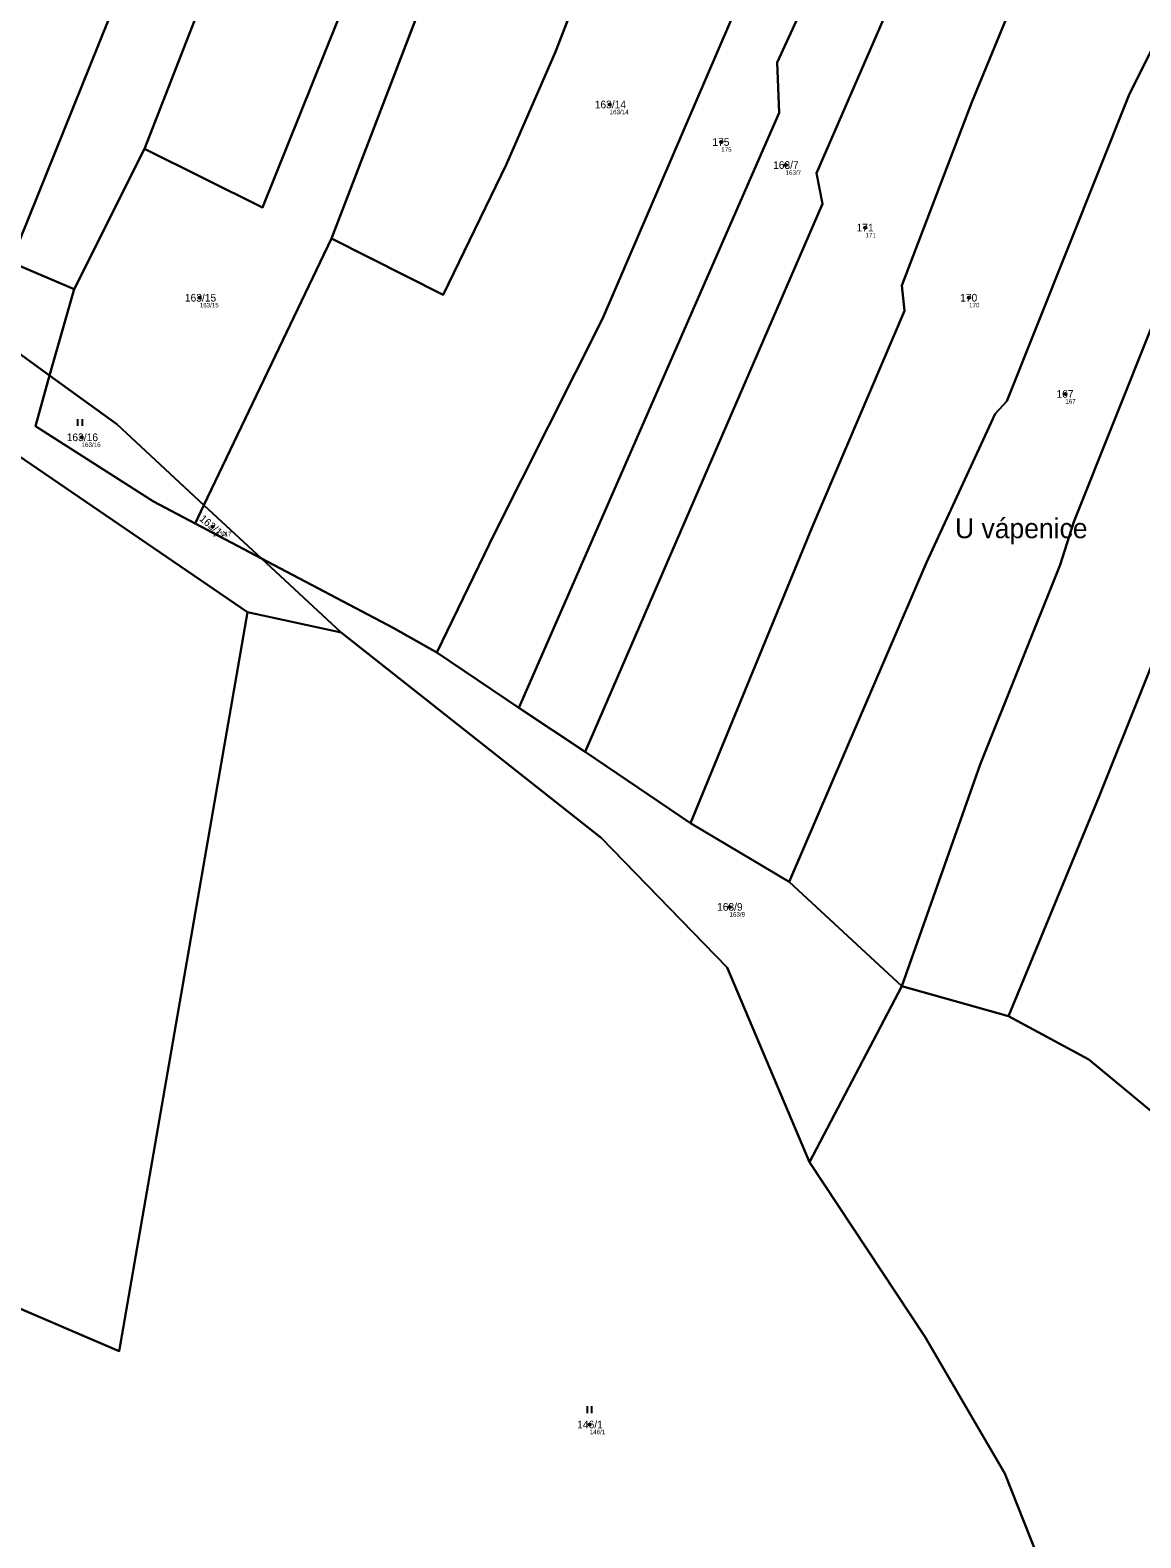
# Model space of a CAD drawing. Extents: x -767985 to -763816, y -1059600 to -1057360.
# Drawn here: x -766260 to -766013.3, y -1058832.2 to -1058497.3 of the extents above; entities that cross this region are included whole.
import ezdxf

# ---------------------------------------------------------------- set-up
doc = ezdxf.new("R2010")
doc.units = 0
for name, color, linetype in [('Definiční body', 7, 'Continuous'), ('Hranice parcel', 7, 'Continuous'), ('Parcelní čísla', 7, 'Continuous'), ('Polygon parcely', 7, 'Continuous'), ('Pop  PČ popisy', 7, 'Continuous'), ('Značky kultur', 7, 'Continuous')]:
    doc.layers.add(name, color=color, linetype=linetype)

msp = doc.modelspace()

# ---------------------------------------------------------------- linework, layer by layer
at = {"layer": 'Definiční body'}
for centre in [(-766131.31, -1058513.78994), (-766106.51, -1058522.11994), (-766092.23, -1058527.22994), (-766074.48, -1058541.13994), (-766222.35, -1058556.70994), (-766051.47, -1058556.69994), (-766030.08, -1058578.07994), (-766248.59, -1058587.70994), (-766219.52, -1058607.53994), (-766104.67, -1058692.02994), (-766135.73, -1058807.00994)]:
    msp.add_circle(centre, 0.25, dxfattribs=at)
at = {"layer": 'Hranice parcel'}
for p, q in [((-766166.97, -1058350.08), (-766234.65, -1058523.62)), ((-766193.09, -1058543.53), (-766125.82, -1058368.4)), ((-766234.65, -1058523.62), (-766250.27, -1058554.82)), ((-766193.09, -1058543.53), (-766221.41, -1058602.76)), ((-766250.27, -1058554.82), (-766264.31, -1058548.78)), ((-766255.7, -1058573.98), (-766250.27, -1058554.82)), ((-766223.37, -1058606.85), (-766221.41, -1058602.76)), ((-766221.41, -1058602.76), (-766208.62, -1058614.63)), ((-766208.62, -1058614.63), (-766223.37, -1058606.85)), ((-766190.92, -1058631.06), (-766208.62, -1058614.63)), ((-766190.92, -1058631.06), (-766211.76, -1058626.58)), ((-766151.49, -1058647.82), (-766169.69, -1058635.49)), ((-766151.49, -1058647.82), (-766136.72, -1058657.61)), ((-766113.32, -1058673.4), (-766136.72, -1058657.61)), ((-766091.43, -1058686.48), (-766113.32, -1058673.4)), ((-766066.43, -1058709.63), (-766091.43, -1058686.48)), ((-766086.92, -1058748.74), (-766066.43, -1058709.63)), ((-766042.69, -1058716.31), (-766066.43, -1058709.63))]:
    msp.add_line(p, q, dxfattribs=at)
for points in [[(-766183.72, -1058343.65), (-766211.11, -1058416.66), (-766264.31, -1058548.78)], [(-766142.57, -1058362.31), (-766161.12, -1058418.9), (-766208.41, -1058536.69), (-766234.65, -1058523.62)], [(-766095.42, -1058382.27), (-766113.31, -1058432.89), (-766116.58, -1058432.79), (-766143.3, -1058502.05), (-766154.19, -1058527.06), (-766168.29, -1058556.08), (-766193.09, -1058543.53)], [(-766169.69, -1058635.49), (-766156.91, -1058609.08), (-766132.92, -1058561.4), (-766102, -1058489.55), (-766103.74, -1058482.68), (-766090.42, -1058451.4), (-766067.85, -1058388.57)], [(-766049.88, -1058400.36), (-766058.24, -1058416.78), (-766061.82, -1058434.27), (-766094.09, -1058504.46), (-766093.62, -1058515.66), (-766151.49, -1058647.82)], [(-766136.72, -1058657.61), (-766084.02, -1058535.83), (-766085.34, -1058529.05), (-766034.52, -1058412.06)], [(-766016.38, -1058429.41), (-766050.83, -1058513.25), (-766066.39, -1058553.96), (-766065.8, -1058559.59), (-766086.3, -1058607.64), (-766113.32, -1058673.4)], [(-765987.29, -1058454.03), (-766015.99, -1058511.79), (-766043.07, -1058579.66), (-766045.7, -1058582.49), (-766060.94, -1058615.53), (-766091.43, -1058686.48)], [(-765970.97, -1058467.85), (-765992.67, -1058517.5), (-766028.19, -1058606.49), (-766031.26, -1058616.02), (-766049.02, -1058660.43), (-766066.43, -1058709.63)], [(-765949.24, -1058486.24), (-765967.46, -1058526.34), (-765975.64, -1058550.3), (-766022.63, -1058667.68), (-766042.69, -1058716.31)], [(-766255.7, -1058573.98), (-766275.75, -1058559.47), (-766301.66, -1058544.49), (-766328.07, -1058536.37)], [(-766211.76, -1058626.58), (-766295.71, -1058569.25), (-766331.39, -1058552.99)], [(-766223.37, -1058606.85), (-766232.59, -1058601.99), (-766258.8, -1058585.21), (-766255.7, -1058573.98)], [(-766255.7, -1058573.98), (-766240.75, -1058584.79), (-766221.41, -1058602.76)], [(-766169.69, -1058635.49), (-766179.38, -1058630.04), (-766208.62, -1058614.63)], [(-766211.76, -1058626.58), (-766240.25, -1058790.7), (-766291.42, -1058768.8), (-766295.87, -1058866.16)], [(-766086.92, -1058748.74), (-766105.2, -1058705.47), (-766133.16, -1058676.71), (-766190.92, -1058631.06)], [(-765997.26, -1058748.82), (-766024.85, -1058725.9), (-766042.69, -1058716.31)], [(-766036.35, -1058836.05), (-766043.51, -1058817.88), (-766061.32, -1058787.45), (-766086.92, -1058748.74)]]:
    msp.add_lwpolyline(points, dxfattribs=at)
at = {"layer": 'Polygon parcely'}
for points in [[(-766232.74, -1058341.71), (-766245.07, -1058376.23), (-766257.82, -1058412.17), (-766297.34, -1058510.12), (-766306.29, -1058534.69), (-766264.31, -1058548.78), (-766211.11, -1058416.66), (-766183.72, -1058343.65), (-766189.66, -1058341.37), (-766201.31, -1058339.04)], [(-766264.31, -1058548.78), (-766250.27, -1058554.82), (-766234.65, -1058523.62), (-766166.97, -1058350.08), (-766183.72, -1058343.65), (-766211.11, -1058416.66)], [(-766234.65, -1058523.62), (-766208.41, -1058536.69), (-766161.12, -1058418.9), (-766142.57, -1058362.31), (-766166.97, -1058350.08)], [(-766193.09, -1058543.53), (-766125.82, -1058368.4), (-766142.57, -1058362.31), (-766161.12, -1058418.9), (-766208.41, -1058536.69), (-766234.65, -1058523.62), (-766250.27, -1058554.82), (-766255.7, -1058573.98), (-766240.75, -1058584.79), (-766221.41, -1058602.76)], [(-766193.09, -1058543.53), (-766168.29, -1058556.08), (-766154.19, -1058527.06), (-766143.3, -1058502.05), (-766116.58, -1058432.79), (-766113.31, -1058432.89), (-766095.42, -1058382.27), (-766122.29, -1058369.54), (-766125.82, -1058368.4)], [(-766103.74, -1058482.68), (-766090.42, -1058451.4), (-766067.85, -1058388.57), (-766095.42, -1058382.27), (-766113.31, -1058432.89), (-766116.58, -1058432.79), (-766143.3, -1058502.05), (-766154.19, -1058527.06), (-766168.29, -1058556.08), (-766193.09, -1058543.53), (-766221.41, -1058602.76), (-766208.62, -1058614.63), (-766179.38, -1058630.04), (-766169.69, -1058635.49), (-766156.91, -1058609.08), (-766132.92, -1058561.4), (-766102, -1058489.55)], [(-766067.85, -1058388.57), (-766090.42, -1058451.4), (-766103.74, -1058482.68), (-766102, -1058489.55), (-766132.92, -1058561.4), (-766156.91, -1058609.08), (-766169.69, -1058635.49), (-766151.49, -1058647.82), (-766093.62, -1058515.66), (-766094.09, -1058504.46), (-766061.82, -1058434.27), (-766058.24, -1058416.78), (-766049.88, -1058400.36)], [(-766093.62, -1058515.66), (-766151.49, -1058647.82), (-766136.72, -1058657.61), (-766084.02, -1058535.83), (-766085.34, -1058529.05), (-766034.52, -1058412.06), (-766049.88, -1058400.36), (-766058.24, -1058416.78), (-766061.82, -1058434.27), (-766094.09, -1058504.46)], [(-766034.52, -1058412.06), (-766085.34, -1058529.05), (-766084.02, -1058535.83), (-766136.72, -1058657.61), (-766113.32, -1058673.4), (-766086.3, -1058607.64), (-766065.8, -1058559.59), (-766066.39, -1058553.96), (-766050.83, -1058513.25), (-766016.38, -1058429.41)], [(-766066.39, -1058553.96), (-766065.8, -1058559.59), (-766086.3, -1058607.64), (-766113.32, -1058673.4), (-766091.43, -1058686.48), (-766060.94, -1058615.53), (-766045.7, -1058582.49), (-766043.07, -1058579.66), (-766015.99, -1058511.79), (-765987.29, -1058454.03), (-766016.38, -1058429.41), (-766050.83, -1058513.25)], [(-766091.43, -1058686.48), (-766066.43, -1058709.63), (-766049.02, -1058660.43), (-766031.26, -1058616.02), (-766028.19, -1058606.49), (-765992.67, -1058517.5), (-765970.97, -1058467.85), (-765987.29, -1058454.03), (-766015.99, -1058511.79), (-766043.07, -1058579.66), (-766045.7, -1058582.49), (-766060.94, -1058615.53)], [(-765970.97, -1058467.85), (-765992.67, -1058517.5), (-766028.19, -1058606.49), (-766031.26, -1058616.02), (-766049.02, -1058660.43), (-766066.43, -1058709.63), (-766042.69, -1058716.31), (-766022.63, -1058667.68), (-765975.64, -1058550.3), (-765967.46, -1058526.34), (-765949.24, -1058486.24)], [(-765967.46, -1058526.34), (-765975.64, -1058550.3), (-766022.63, -1058667.68), (-766042.69, -1058716.31), (-766024.85, -1058725.9), (-765997.26, -1058748.82), (-765970.63, -1058682.65), (-765969.81, -1058676.38), (-765955.46, -1058639.14), (-765946.75, -1058613.53), (-765930.78, -1058556.44), (-765915.25, -1058521.03), (-765939.32, -1058499.61), (-765949.24, -1058486.24)], [(-766255.7, -1058573.98), (-766250.27, -1058554.82), (-766264.31, -1058548.78), (-766306.29, -1058534.69), (-766326.8, -1058528.57), (-766328.07, -1058536.37), (-766301.66, -1058544.49), (-766275.75, -1058559.47)], [(-766275.75, -1058559.47), (-766301.66, -1058544.49), (-766328.07, -1058536.37), (-766331.39, -1058552.99), (-766295.71, -1058569.25), (-766211.76, -1058626.58), (-766190.92, -1058631.06), (-766208.62, -1058614.63), (-766223.37, -1058606.85), (-766232.59, -1058601.99), (-766258.8, -1058585.21), (-766255.7, -1058573.98)], [(-766414.42, -1059025.94), (-766275.96, -1059094.12), (-766230.65, -1059105.14), (-766173.04, -1059080.96), (-766121.91, -1059049.2), (-766045.16, -1058994.51), (-766083.75, -1058956.81), (-766100.88, -1058950.86), (-766125.89, -1058944.9), (-766144.11, -1058934.09), (-766179.37, -1058898.45), (-766255.4, -1058872.06), (-766296.01, -1058869.17), (-766295.87, -1058866.16), (-766291.42, -1058768.8), (-766240.25, -1058790.7), (-766211.76, -1058626.58), (-766295.71, -1058569.25), (-766331.39, -1058552.99), (-766337.3, -1058585.5), (-766342.28, -1058615.61), (-766362.61, -1058728.92), (-766383.18, -1058843.53), (-766412.33, -1059013.73)], [(-766223.37, -1058606.85), (-766221.41, -1058602.76), (-766240.75, -1058584.79), (-766255.7, -1058573.98), (-766258.8, -1058585.21), (-766232.59, -1058601.99)], [(-766223.37, -1058606.85), (-766208.62, -1058614.63), (-766221.41, -1058602.76)], [(-766091.43, -1058686.48), (-766113.32, -1058673.4), (-766136.72, -1058657.61), (-766151.49, -1058647.82), (-766169.69, -1058635.49), (-766179.38, -1058630.04), (-766208.62, -1058614.63), (-766190.92, -1058631.06), (-766133.16, -1058676.71), (-766105.2, -1058705.47), (-766086.92, -1058748.74), (-766066.43, -1058709.63)], [(-766253.94, -1058868.83), (-766176.76, -1058895.38), (-766140.7, -1058932.02), (-766123.69, -1058942.12), (-766105.38, -1058945.95), (-766081.08, -1058953.43), (-766041.83, -1058991.11), (-766024.21, -1058996.57), (-766030.81, -1058910.26), (-766036.35, -1058836.05), (-766043.51, -1058817.88), (-766061.32, -1058787.45), (-766086.92, -1058748.74), (-766105.2, -1058705.47), (-766133.16, -1058676.71), (-766190.92, -1058631.06), (-766211.76, -1058626.58), (-766240.25, -1058790.7), (-766291.42, -1058768.8), (-766295.87, -1058866.16)]]:
    msp.add_lwpolyline(points, close=True, dxfattribs=at)
msp.add_lwpolyline([(-765917.53, -1058849.08), (-765897.38, -1058781.02), (-765917.32, -1058774.2), (-765933.27, -1058771.98), (-765943.72, -1058771.9), (-765967.51, -1058781.41), (-765975.45, -1058772.71), (-765997.26, -1058748.82), (-766024.85, -1058725.9), (-766042.69, -1058716.31), (-766066.43, -1058709.63), (-766086.92, -1058748.74), (-766061.32, -1058787.45), (-766043.51, -1058817.88), (-766036.35, -1058836.05)], dxfattribs=at)
at = {"layer": 'Značky kultur'}
for p, q in [((-766249.421, -1058585.17), (-766249.421, -1058583.67)), ((-766248.42, -1058585.17), (-766248.42, -1058583.67)), ((-766136.241, -1058804.46), (-766136.241, -1058802.96)), ((-766135.24, -1058804.46), (-766135.24, -1058802.96))]:
    msp.add_line(p, q, dxfattribs=at)

# ---------------------------------------------------------------- texts
at = {"layer": 'Definiční body'}
for s, p in [('163/14', (-766131.31, -1058515.946)), ('175', (-766106.51, -1058524.276)), ('163/7', (-766092.23, -1058529.386)), ('171', (-766074.48, -1058543.296)), ('163/15', (-766222.35, -1058558.866)), ('170', (-766051.47, -1058558.856)), ('167', (-766030.08, -1058580.236)), ('163/16', (-766248.59, -1058589.866)), ('163/17', (-766219.52, -1058609.696)), ('163/9', (-766104.67, -1058694.186)), ('146/1', (-766135.73, -1058809.166))]:
    msp.add_text(s, height=0.999996, dxfattribs=at).set_placement(p)
at = {"layer": 'Parcelní čísla'}
for s, p in [('163/14', (-766134.615, -1058514.64)), ('175', (-766108.484, -1058522.97)), ('163/7', (-766095.003, -1058528.08)), ('171', (-766076.454, -1058541.99)), ('163/15', (-766225.655, -1058557.56)), ('170', (-766053.444, -1058557.55)), ('167', (-766032.054, -1058578.93)), ('163/16', (-766251.895, -1058588.56)), ('163/9', (-766107.443, -1058692.88)), ('146/1', (-766138.503, -1058807.86))]:
    msp.add_text(s, height=1.699998, dxfattribs=at).set_placement(p)
msp.add_text('163/17', height=1.699998, rotation=319, dxfattribs=at).set_placement((-766222.572, -1058606.012))
at = {"layer": 'Pop  PČ popisy'}
msp.add_text('U vápenice', height=4.399998, dxfattribs=at).set_placement((-766054.58, -1058610.129))

doc.saveas('drawing.dxf')
